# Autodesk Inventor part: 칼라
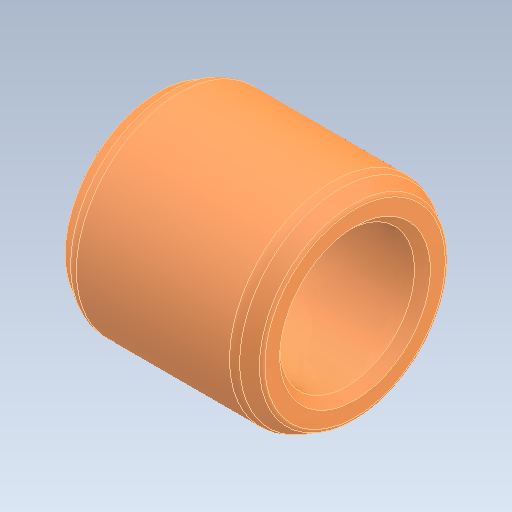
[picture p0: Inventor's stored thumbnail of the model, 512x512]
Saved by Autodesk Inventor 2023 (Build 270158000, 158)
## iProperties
Created: 2025-03
Part Number: 칼라
Material: 강철, 연강
Document SubType Name: Modeling
Designer: Admin
Density: 7.86 g/cm^3
Appearance: 기본값
Author: jhkim
Sending System: Autodesk Inventor 2025
Preprocessor: ST-DEVELOPER v20
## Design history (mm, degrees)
feature "솔리드1"
node "솔리드2"
